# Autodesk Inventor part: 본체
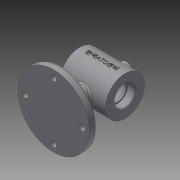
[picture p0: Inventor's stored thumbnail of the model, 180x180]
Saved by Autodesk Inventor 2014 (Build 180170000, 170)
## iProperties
Created: 2018-12
Part Number: 본체
Material: 일반
Document SubType Name: Modeling
Designer: 601-23
Density: 1 g/cm^3
Appearance: 기본값
Mass: 253.737 g
Surface Area: 555.482 cm^2
Volume: 253.737 cm^3
Author: 601-23
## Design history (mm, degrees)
sketch "스케치1"
  geometry: L1 (-35, 0)-(35, 0); L2 (-35, 30)-(35, 30); L3 (35, 30)-(35, 16); L4 (35, 16)-(23, 16); L5 (20, 25)-(-20, 25); L6 (-23, 16)-(-35, 16); L7 (-35, 16)-(-35, 30); L8 (-23, 16)-(-23, 14); L9 (-23, 14)-(-20, 14); L10 (-20, 14)-(-20, 25); L11 (23, 16)-(23, 14); L12 (23, 14)-(20, 14); L13 (20, 14)-(20, 25); 2 further points
  constraints: 26 end point, 7 parallel, 4 perpendicular, 2 vertical alignment, 1 coincident, 1 horizontal, 1 midpoint
  dimensions: "d0" = 70 distance of L1.start L1.end; "d1" = 60 diameter of L2 L1; "d2" = 32 diameter of L6 L1; "d3" = 50 diameter of L5 L1; "d4" = 32 diameter of L4 L1; "d5" = 12 distance of L6.start L6.end; "d6" = 12 distance of L3.end L4.end; "d57" = 28 diameter of L9 L1; "d58" = 28 diameter of L12 L1; "d59" = 3 distance of L8.end L9.end; "d60" = 3 distance of L11.end L12.end
revolve "회전1" sketch "스케치1" stored, may be unused: angle "d7" = 90 deg
node "작업 평면1"
sketch "스케치2"
  geometry: C1 r 55 at (0, 0); 1 further point
  constraints: 1 centre point, 1 coincident
  dimensions: "d9" = 110 diameter of C1
extrude "돌출1" join sketch "스케치2" distance "d10" = 11; taper "d11" = 0 deg
sketch "스케치3"
  geometry: L1 (55, -64)-(-55, -64) reference; L2 (-55, -64)-(-12, -52.478); L3 (-55, -75)-(-55, -64) reference; L4 (55, -75)-(55, -64) reference; L5 (-12, -52.478)-(0, -52.478); L6 (0, -52.478)-(0, -74); L7 (-55, -64)-(0, -64); 1 further point
  constraints: 8 end point, 2 perpendicular, 1 midpoint, 1 point on line
  dimensions: "d12" = 75 deg angle of L3 L2
revolve "회전2" sketch "스케치3" stored, may be unused: angle "d15" = 90 deg
sketch "스케치4" dims "d16" = 88
  geometry: C1 r 55 at (0, 0) reference; 2 further points
  constraints: 2 vertical alignment, 1 coincident, 2 other
hole "구멍1" sketch "스케치4" at (0, 44) diameter "d17" = 9; stored, may be unused: countersink angle "d21" = 90 deg, drill point angle "d23" = 118 deg; dims "d18" = 6, "d19" = 14, "d20" = 10, "d22" = 8
sketch "스케치5"
  geometry: L1 (-62.258, 48.5)-(-75, 48.5) reference; L2 (-59.847, 39.5)-(-75, 39.5) reference; L3 (-75, 39.5)-(-75, 48.5) reference; L4 (-75, 44)-(-57.289, 44); L5 (-57.289, 44)-(-57.289, 51); L6 (-57.289, 51)-(-65, 51); L7 (-65, 44)-(-65, 51); 1 further point
  constraints: 8 end point, 4 perpendicular, 1 midpoint, 1 point on line
  dimensions: "d24" = 7 distance of L4.end L5.end; "d25" = 10 distance between parallel lines of L3 L7
revolve "회전3" sketch "스케치5" stored, may be unused: angle "d26" = 90 deg
sketch "스케치6"
  geometry: C1 r 12 at (0, 0) reference; C2 r 12 at (0, 0)
  constraints: 1 centre point, 1 coincident
  dimensions: "d30" = 24 diameter of C2
extrude "돌출2" join sketch "스케치6" stored distance "d31" = 10; taper "d32" = 0 deg
node "작업 평면2"
sketch "스케치7"
  geometry: C1 r 10 at (0, 0); 1 further point
  constraints: 1 centre point, 1 coincident
  dimensions: "d34" = 20 diameter of C1
extrude "돌출3" join sketch "스케치7" stored distance "d35" = 10; taper "d36" = 0 deg
hole "구멍2" diameter "d39" = 10; stored, may be unused: countersink angle "d43" = 90 deg, drill point angle "d45" = 118 deg; dims "d37" = 10, "d38" = 10, "d40" = 6, "d41" = 14, "d42" = 10, "d44" = 8
sketch "스케치8"
  geometry: C1 r 30 at (0, 0) reference; 1 further point
  constraints: 1 vertical alignment
  dimensions: "d46" = 23 distance of C1.centre point (0, 23)
hole "구멍3" sketch "스케치8" at (0, 23) diameter "d47" = 3.242; stored, may be unused: countersink angle "d51" = 90 deg, drill point angle "d53" = 118 deg; dims "d48" = 8, "d49" = 14, "d50" = 10, "d52" = 10
fillet "모깎기1" dims "d61" = 0.3
fillet "모깎기2" dims "d62" = 3
chamfer "모따기1" distance "d63" = 1; stored, may be unused: second distance "d64" = 2, angle "d65" = 45 deg
node "작업 평면4"
sketch "스케치10"
  geometry: L1 (-35, -30)-(-35, 30) reference; 2 further points
  constraints: 1 other
  dimensions: "d70" = 35 distance from line of L1 point (0, 0); "d71" = 30 vertical distance of L1.end point (0, 0)
feature "엠보싱1" sketch "스케치10" dims "d12" = 75 deg, "d72" = 0.5, "d73" = 0
node "솔리드1"
pattern_circular "원형 패턴1" dims angle "d28" = 360 deg
pattern_circular "원형 패턴2" dims angle "d55" = 360 deg
mirror "대칭1"
other parameters: "d8" = -75, "d33" = 37, "d69" = 49.5
